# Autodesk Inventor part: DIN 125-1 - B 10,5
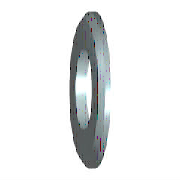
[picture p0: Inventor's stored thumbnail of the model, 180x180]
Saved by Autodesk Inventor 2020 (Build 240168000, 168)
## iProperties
Created: 2010-02
Part Number: DIN 125-1 - B 10,5
Material: Steel, Mild
Document SubType Name: Modeling
Standard: DIN 125-1
Designer: DLutz
Standards Organization: DIN
Language: de-DE
Size Designation: B 10,5
Categories: <MemberInstance><Categories><Category DisplayName="Verbindungselemente" InternalName="e4da775c-781d-43d5-af7c-5136215cf5a6" Mnemonic="FSTN"><Category DisplayNam
Mass: 3.51668 g
Surface Area: 6.28047 cm^2
Volume: 0.447415 cm^3
Density: 7.86 g/cm^3
Appearance: Metal-Steel
IsCustomPart: 0
Author: DLutz
Revision Number: C
Title: Unterlegscheibe
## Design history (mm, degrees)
body "Solid1"
sketch "Sketch"
  geometry: C1 r 10 at (0, 0); C2 r 5.25 at (0, 0); 1 further point
  constraints: 2 centre point, 2 coincident
  dimensions: "d0" = 10.5 diameter of C2 (= SD1); "d1" = 20 diameter of C1 (= SD2)
extrude "Body" new body sketch "Sketch" distance "d2" = 2 (= SD); taper "d3" = 0 deg
chamfer "Chamfer" distance "d4" = 0.5 (= PHH); stored, may be unused: angle "d5" = 45 deg, second distance "d8" = 0.5 (= PHH)
workaxis "Work Axis1"
workplane "Work Plane1"
other parameters: "SD1" = 10.5 [user parameter; used in 1 equation term], "SD2" = 20 [user parameter; used in 1 equation term], "SD" = 2 [user parameter; used in 1 equation term], "PHH" = 0.5 [user parameter; used in 2 equation terms], "FAWI" = 45 deg [user parameter], "d6" = 0, "d7" = 0, "d9" = 0, "d10" = 0
